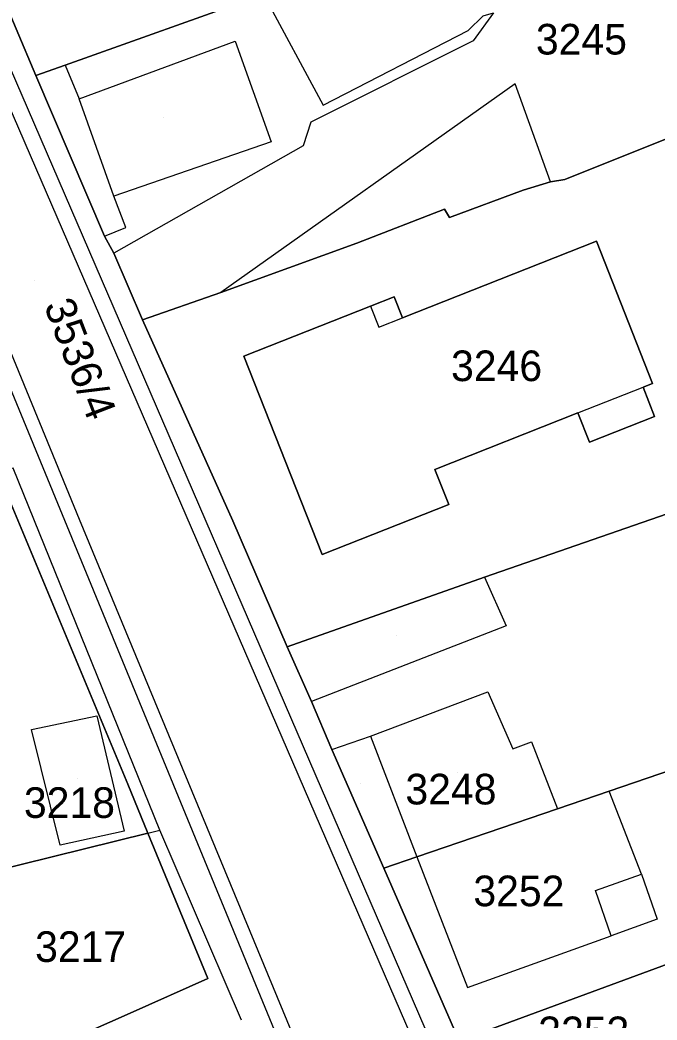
# Model space of a CAD drawing. Extents: x -262657 to -261595, y -1238015 to -1237156.
# Drawn here: x -261921.2 to -261879.5, y -1237814 to -1237748.7 of the extents above; entities that cross this region are included whole.
import ezdxf

# ---------------------------------------------------------------- set-up
doc = ezdxf.new("R2010")
doc.units = 0
for name, color, linetype in [('body_kn', 7, 'Continuous'), ('kladpar_druhypozemkov', 7, 'Continuous'), ('kladpar_hranice', 7, 'Continuous'), ('kladpar_parcelnecisla', 7, 'Continuous'), ('kladpar_plochy', 7, 'Continuous'), ('zappar_hrandruhpozemk', 7, 'Continuous')]:
    doc.layers.add(name, color=color, linetype=linetype)

msp = doc.modelspace()

# ---------------------------------------------------------------- linework, layer by layer
at = {"layer": 'body_kn'}
for p, q in [((-261891.88, -1237749.38), (-261891.88, -1237749.38)), ((-261907.09, -1237750.06), (-261907.09, -1237750.06)), ((-261907.09, -1237750.06), (-261907.09, -1237750.06)), ((-261891.54, -1237750.05), (-261891.54, -1237750.05)), ((-261918.2, -1237751.63), (-261918.2, -1237751.63)), ((-261918.2, -1237751.63), (-261918.2, -1237751.63)), ((-261920.12, -1237752.32), (-261920.12, -1237752.32)), ((-261920.12, -1237752.32), (-261920.12, -1237752.32)), ((-261888.8, -1237752.86), (-261888.8, -1237752.86)), ((-261917.29, -1237753.83), (-261917.29, -1237753.83)), ((-261917.29, -1237753.83), (-261917.29, -1237753.83)), ((-261901.34, -1237754.24), (-261901.34, -1237754.24)), ((-261902.16, -1237755.36), (-261902.16, -1237755.36)), ((-261904.74, -1237756.65), (-261904.74, -1237756.65)), ((-261902.66, -1237756.91), (-261902.66, -1237756.91)), ((-261886.5, -1237759.27), (-261886.5, -1237759.27)), ((-261886.5, -1237759.27), (-261886.5, -1237759.27)), ((-261885.56, -1237759.1), (-261885.56, -1237759.1)), ((-261888.28, -1237759.8), (-261888.28, -1237759.8)), ((-261915.03, -1237760.19), (-261915.03, -1237760.19)), ((-261915.03, -1237760.19), (-261915.03, -1237760.19)), ((-261893.41, -1237761.04), (-261893.41, -1237761.04)), ((-261893.1, -1237761.58), (-261893.1, -1237761.58)), ((-261914.24, -1237762.24), (-261914.24, -1237762.24)), ((-261915.64, -1237762.81), (-261915.64, -1237762.81)), ((-261915.64, -1237762.81), (-261915.64, -1237762.81)), ((-261883.49, -1237763.13), (-261883.49, -1237763.13)), ((-261899.15, -1237763.26), (-261899.15, -1237763.26)), ((-261915.03, -1237763.93), (-261915.03, -1237763.93)), ((-261908.04, -1237766.48), (-261908.04, -1237766.48)), ((-261896.7, -1237766.77), (-261896.7, -1237766.77)), ((-261898.25, -1237767.38), (-261898.25, -1237767.38)), ((-261898.25, -1237767.38), (-261898.25, -1237767.38)), ((-261913.16, -1237768.28), (-261913.16, -1237768.28)), ((-261896.16, -1237768.14), (-261896.16, -1237768.14)), ((-261897.7, -1237768.75), (-261897.7, -1237768.75)), ((-261906.54, -1237770.66), (-261906.54, -1237770.66)), ((-261880.44, -1237772.68), (-261880.44, -1237772.68)), ((-261879.82, -1237772.43), (-261879.82, -1237772.43)), ((-261884.7, -1237774.36), (-261884.7, -1237774.36)), ((-261884.7, -1237774.36), (-261884.7, -1237774.36)), ((-261879.69, -1237774.59), (-261879.69, -1237774.59)), ((-261883.94, -1237776.27), (-261883.94, -1237776.27)), ((-261894.04, -1237778.06), (-261894.04, -1237778.06)), ((-261894.04, -1237778.06), (-261894.04, -1237778.06)), ((-261893.14, -1237780.34), (-261893.14, -1237780.34)), ((-261917.3, -1237781.31), (-261917.3, -1237781.31)), ((-261907.24, -1237781.41), (-261907.24, -1237781.41)), ((-261901.42, -1237783.61), (-261901.42, -1237783.61)), ((-261890.8, -1237785.1), (-261890.8, -1237785.1)), ((-261890.8, -1237785.1), (-261890.8, -1237785.1)), ((-261889.39, -1237788.26), (-261889.39, -1237788.26)), ((-261903.69, -1237789.65), (-261903.69, -1237789.65)), ((-261903.69, -1237789.65), (-261903.69, -1237789.65)), ((-261890.58, -1237792.59), (-261890.58, -1237792.59)), ((-261902.12, -1237793.22), (-261902.12, -1237793.22)), ((-261916.13, -1237794.16), (-261916.13, -1237794.16)), ((-261920.41, -1237795.04), (-261920.41, -1237795.04)), ((-261898.26, -1237795.47), (-261898.26, -1237795.47)), ((-261887.73, -1237795.86), (-261887.73, -1237795.86)), ((-261900.78, -1237796.35), (-261900.78, -1237796.35)), ((-261900.78, -1237796.35), (-261900.78, -1237796.35)), ((-261888.95, -1237796.3), (-261888.95, -1237796.3)), ((-261914.12, -1237798.61), (-261914.12, -1237798.61)), ((-261882.66, -1237799.08), (-261882.66, -1237799.08)), ((-261886.03, -1237800.22), (-261886.03, -1237800.22)), ((-261914.35, -1237801.68), (-261914.35, -1237801.68)), ((-261912.03, -1237801.62), (-261912.03, -1237801.62)), ((-261912.8, -1237801.81), (-261912.8, -1237801.81)), ((-261912.8, -1237801.81), (-261912.8, -1237801.81)), ((-261918.54, -1237802.61), (-261918.54, -1237802.61)), ((-261918.54, -1237802.61), (-261918.54, -1237802.61)), ((-261895.22, -1237803.36), (-261895.22, -1237803.36)), ((-261895.22, -1237803.36), (-261895.22, -1237803.36)), ((-261897.39, -1237804.1), (-261897.39, -1237804.1)), ((-261897.39, -1237804.1), (-261897.39, -1237804.1)), ((-261880.55, -1237804.5), (-261880.55, -1237804.5)), ((-261880.55, -1237804.5), (-261880.55, -1237804.5)), ((-261883.54, -1237805.57), (-261883.54, -1237805.57)), ((-261882.53, -1237808.52), (-261882.53, -1237808.52)), ((-261908.88, -1237811.31), (-261908.88, -1237811.31)), ((-261891.91, -1237811.91), (-261891.91, -1237811.91)), ((-261913.97, -1237813.57), (-261913.97, -1237813.57))]:
    msp.add_line(p, q, dxfattribs=at)
at = {"layer": 'kladpar_druhypozemkov'}
for p, q in [((-261883.39, -1237749.05), (-261883.39, -1237749.05)), ((-261911.75, -1237755.06), (-261911.75, -1237755.06)), ((-261920.19, -1237765.72), (-261920.19, -1237765.72)), ((-261888.45, -1237770.3), (-261888.45, -1237770.3)), ((-261896.55, -1237788.9), (-261896.55, -1237788.9)), ((-261917.39, -1237798.27), (-261917.39, -1237798.27)), ((-261892.55, -1237797.88), (-261892.55, -1237797.88)), ((-261898.9, -1237798.57), (-261898.9, -1237798.57)), ((-261888.4, -1237804.98), (-261888.4, -1237804.98)), ((-261917.24, -1237808.41), (-261917.24, -1237808.41))]:
    msp.add_line(p, q, dxfattribs=at)
at = {"layer": 'kladpar_hranice'}
for points in [[(-261914.09, -1237816.76), (-261923.62, -1237819.21), (-261923.89, -1237818.34), (-261924, -1237817.96), (-261923.67, -1237817.87), (-261913.97, -1237813.57), (-261908.88, -1237811.31), (-261912.8, -1237801.81), (-261914.12, -1237798.61), (-261922.63, -1237778.24), (-261926.09, -1237769.65), (-261929.76, -1237759.16), (-261940.37, -1237728.85), (-261943.02, -1237721.29), (-261943.45, -1237719.94), (-261944.94, -1237715.14), (-261945.5, -1237713.33), (-261947.79, -1237697.89), (-261949.17, -1237690.86), (-261949.54, -1237688.95), (-261951.01, -1237681.71), (-261952.29, -1237673.66)], [(-261920.12, -1237752.32), (-261922.72, -1237746.19), (-261923.24, -1237745.09), (-261924.29, -1237741.53), (-261918.09, -1237739.63), (-261914.17, -1237738.53), (-261911.54, -1237737.64), (-261907.41, -1237736.41), (-261905.24, -1237747), (-261918.2, -1237751.63), (-261920.12, -1237752.32)], [(-261920.12, -1237752.32), (-261918.2, -1237751.63), (-261905.24, -1237747), (-261891.79, -1237742.14), (-261888.53, -1237740.9), (-261888.38, -1237741.32), (-261879.2, -1237737.96), (-261878.19, -1237737.65), (-261876.61, -1237737.16), (-261874.12, -1237742.17), (-261870.26, -1237752.98), (-261885.56, -1237759.1), (-261886.5, -1237759.27), (-261888.28, -1237759.8), (-261893.1, -1237761.58), (-261893.41, -1237761.04), (-261899.15, -1237763.26), (-261908.04, -1237766.48), (-261913.16, -1237768.28), (-261915.03, -1237763.93), (-261915.64, -1237762.81), (-261920.12, -1237752.32)], [(-261922.72, -1237746.19), (-261920.12, -1237752.32), (-261915.64, -1237762.81), (-261915.03, -1237763.93), (-261913.16, -1237768.28), (-261907.24, -1237781.41), (-261903.69, -1237789.65), (-261902.12, -1237793.22), (-261900.78, -1237796.35), (-261897.39, -1237804.1), (-261892.46, -1237815.38)], [(-261913.16, -1237768.28), (-261908.04, -1237766.48), (-261899.15, -1237763.26), (-261893.41, -1237761.04), (-261893.1, -1237761.58), (-261888.28, -1237759.8), (-261886.5, -1237759.27), (-261885.56, -1237759.1), (-261870.26, -1237752.98), (-261869.5, -1237752.69), (-261860.68, -1237774.55), (-261863.1, -1237775.49), (-261890.8, -1237785.1), (-261903.69, -1237789.65)], [(-261906.54, -1237770.66), (-261901.42, -1237783.61), (-261893.14, -1237780.34), (-261894.04, -1237778.06), (-261884.7, -1237774.36), (-261883.94, -1237776.27), (-261879.69, -1237774.59), (-261880.44, -1237772.68), (-261879.82, -1237772.43), (-261883.49, -1237763.13), (-261896.16, -1237768.14), (-261896.7, -1237766.77), (-261898.25, -1237767.38), (-261906.54, -1237770.66)], [(-261894.04, -1237778.06), (-261893.14, -1237780.34), (-261901.42, -1237783.61), (-261906.54, -1237770.66), (-261898.25, -1237767.38), (-261896.7, -1237766.77), (-261896.16, -1237768.14), (-261883.49, -1237763.13), (-261879.82, -1237772.43), (-261880.44, -1237772.68), (-261879.69, -1237774.59), (-261883.94, -1237776.27), (-261884.7, -1237774.36), (-261894.04, -1237778.06)], [(-261903.69, -1237789.65), (-261907.24, -1237781.41), (-261913.16, -1237768.28)], [(-261897.39, -1237804.1), (-261900.78, -1237796.35), (-261902.12, -1237793.22), (-261903.69, -1237789.65), (-261890.8, -1237785.1), (-261863.1, -1237775.49), (-261860.84, -1237781.14), (-261874.19, -1237785.8), (-261871.08, -1237795.12), (-261875.2, -1237796.53), (-261882.66, -1237799.08), (-261886.03, -1237800.22), (-261895.22, -1237803.36), (-261897.39, -1237804.1)], [(-261925.24, -1237804.88), (-261927.57, -1237779.48), (-261922.63, -1237778.24), (-261914.12, -1237798.61), (-261912.8, -1237801.81), (-261925.24, -1237804.88)], [(-261892.46, -1237815.38), (-261897.39, -1237804.1), (-261895.22, -1237803.36), (-261886.03, -1237800.22), (-261882.66, -1237799.08), (-261875.2, -1237796.53), (-261874.46, -1237799.37), (-261878.83, -1237801.48), (-261876.32, -1237809.44), (-261892.46, -1237815.38)], [(-261924.11, -1237817.62), (-261925.24, -1237804.88), (-261912.8, -1237801.81), (-261908.88, -1237811.31), (-261913.97, -1237813.57), (-261923.67, -1237817.87), (-261924, -1237817.96), (-261924.11, -1237817.62)], [(-261890.38, -1237820.3), (-261892.46, -1237815.38), (-261876.32, -1237809.44), (-261874, -1237808.64), (-261873.82, -1237809.05), (-261875.21, -1237809.56), (-261873.73, -1237813.58), (-261875.04, -1237813.91), (-261878.43, -1237816.1), (-261890.38, -1237820.3)]]:
    msp.add_lwpolyline(points, dxfattribs=at)
at = {"layer": 'kladpar_plochy'}
for p, q in [((-261885.56, -1237759.1), (-261870.26, -1237752.98)), ((-261888.28, -1237759.8), (-261886.5, -1237759.27)), ((-261886.5, -1237759.27), (-261885.56, -1237759.1)), ((-261893.1, -1237761.58), (-261888.28, -1237759.8)), ((-261899.15, -1237763.26), (-261893.41, -1237761.04)), ((-261893.41, -1237761.04), (-261893.1, -1237761.58)), ((-261883.49, -1237763.13), (-261896.16, -1237768.14)), ((-261879.82, -1237772.43), (-261883.49, -1237763.13)), ((-261908.04, -1237766.48), (-261899.15, -1237763.26)), ((-261913.16, -1237768.28), (-261908.04, -1237766.48)), ((-261896.7, -1237766.77), (-261898.25, -1237767.38)), ((-261896.16, -1237768.14), (-261896.7, -1237766.77)), ((-261898.25, -1237767.38), (-261906.54, -1237770.66)), ((-261907.24, -1237781.41), (-261913.16, -1237768.28)), ((-261906.54, -1237770.66), (-261901.42, -1237783.61)), ((-261880.44, -1237772.68), (-261879.82, -1237772.43)), ((-261879.69, -1237774.59), (-261880.44, -1237772.68)), ((-261894.04, -1237778.06), (-261884.7, -1237774.36)), ((-261884.7, -1237774.36), (-261883.94, -1237776.27)), ((-261883.94, -1237776.27), (-261879.69, -1237774.59)), ((-261863.1, -1237775.49), (-261890.8, -1237785.1)), ((-261893.14, -1237780.34), (-261894.04, -1237778.06)), ((-261901.42, -1237783.61), (-261893.14, -1237780.34)), ((-261903.69, -1237789.65), (-261907.24, -1237781.41)), ((-261890.8, -1237785.1), (-261903.69, -1237789.65))]:
    msp.add_line(p, q, dxfattribs=at)
for points in [[(-261923.67, -1237817.87), (-261913.97, -1237813.57), (-261908.88, -1237811.31), (-261912.8, -1237801.81), (-261914.12, -1237798.61), (-261922.63, -1237778.24), (-261926.09, -1237769.65), (-261929.76, -1237759.16), (-261940.37, -1237728.85)], [(-261922.72, -1237746.19), (-261920.12, -1237752.32), (-261915.64, -1237762.81), (-261915.03, -1237763.93), (-261913.16, -1237768.28), (-261907.24, -1237781.41), (-261903.69, -1237789.65), (-261902.12, -1237793.22), (-261900.78, -1237796.35), (-261897.39, -1237804.1), (-261892.46, -1237815.38)]]:
    msp.add_lwpolyline(points, dxfattribs=at)
for points in [[(-261920.12, -1237752.32), (-261922.72, -1237746.19), (-261923.24, -1237745.09), (-261924.29, -1237741.53), (-261918.09, -1237739.63), (-261914.17, -1237738.53), (-261911.54, -1237737.64), (-261907.41, -1237736.41), (-261905.24, -1237747), (-261918.2, -1237751.63)], [(-261920.12, -1237752.32), (-261918.2, -1237751.63), (-261905.24, -1237747), (-261891.79, -1237742.14), (-261888.53, -1237740.9), (-261888.38, -1237741.32), (-261879.2, -1237737.96), (-261878.19, -1237737.65), (-261876.61, -1237737.16), (-261874.12, -1237742.17), (-261870.26, -1237752.98), (-261885.56, -1237759.1), (-261886.5, -1237759.27), (-261888.28, -1237759.8), (-261893.1, -1237761.58), (-261893.41, -1237761.04), (-261899.15, -1237763.26), (-261908.04, -1237766.48), (-261913.16, -1237768.28), (-261915.03, -1237763.93), (-261915.64, -1237762.81)], [(-261894.04, -1237778.06), (-261893.14, -1237780.34), (-261901.42, -1237783.61), (-261906.54, -1237770.66), (-261898.25, -1237767.38), (-261896.7, -1237766.77), (-261896.16, -1237768.14), (-261883.49, -1237763.13), (-261879.82, -1237772.43), (-261880.44, -1237772.68), (-261879.69, -1237774.59), (-261883.94, -1237776.27), (-261884.7, -1237774.36)], [(-261897.39, -1237804.1), (-261900.78, -1237796.35), (-261902.12, -1237793.22), (-261903.69, -1237789.65), (-261890.8, -1237785.1), (-261863.1, -1237775.49), (-261860.84, -1237781.14), (-261874.19, -1237785.8), (-261871.08, -1237795.12), (-261875.2, -1237796.53), (-261882.66, -1237799.08), (-261886.03, -1237800.22), (-261895.22, -1237803.36)], [(-261925.24, -1237804.88), (-261927.57, -1237779.48), (-261922.63, -1237778.24), (-261914.12, -1237798.61), (-261912.8, -1237801.81)], [(-261892.46, -1237815.38), (-261897.39, -1237804.1), (-261895.22, -1237803.36), (-261886.03, -1237800.22), (-261882.66, -1237799.08), (-261875.2, -1237796.53), (-261874.46, -1237799.37), (-261878.83, -1237801.48), (-261876.32, -1237809.44)], [(-261924.11, -1237817.62), (-261925.24, -1237804.88), (-261912.8, -1237801.81), (-261908.88, -1237811.31), (-261913.97, -1237813.57), (-261923.67, -1237817.87), (-261924, -1237817.96)], [(-261890.38, -1237820.3), (-261892.46, -1237815.38), (-261876.32, -1237809.44), (-261874, -1237808.64), (-261873.82, -1237809.05), (-261875.21, -1237809.56), (-261873.73, -1237813.58), (-261875.04, -1237813.91), (-261878.43, -1237816.1)]]:
    msp.add_lwpolyline(points, close=True, dxfattribs=at)
at = {"layer": 'zappar_hrandruhpozemk'}
for p, q in [((-261924.51, -1237745.6), (-261870.74, -1237869.97)), ((-261917.29, -1237753.83), (-261907.09, -1237750.06)), ((-261907.09, -1237750.06), (-261904.74, -1237756.65)), ((-261918.2, -1237751.63), (-261917.29, -1237753.83)), ((-261888.8, -1237752.86), (-261908.04, -1237766.48)), ((-261886.5, -1237759.27), (-261888.8, -1237752.86)), ((-261915.03, -1237760.19), (-261917.29, -1237753.83)), ((-261904.74, -1237756.65), (-261915.03, -1237760.19)), ((-261902.66, -1237756.91), (-261915.03, -1237763.93)), ((-261926.63, -1237758.6), (-261917.3, -1237781.31)), ((-261898.25, -1237767.38), (-261897.7, -1237768.75)), ((-261897.7, -1237768.75), (-261896.16, -1237768.14)), ((-261884.7, -1237774.36), (-261880.44, -1237772.68)), ((-261890.8, -1237785.1), (-261889.39, -1237788.26)), ((-261889.39, -1237788.26), (-261902.12, -1237793.22)), ((-261918.54, -1237802.61), (-261920.41, -1237795.04)), ((-261900.78, -1237796.35), (-261898.26, -1237795.47)), ((-261898.26, -1237795.47), (-261895.22, -1237803.36)), ((-261906.69, -1237814.03), (-261912.03, -1237801.62)), ((-261895.22, -1237803.36), (-261891.91, -1237811.91))]:
    msp.add_line(p, q, dxfattribs=at)
for points in [[(-261857.29, -1237903.53), (-261871.7, -1237870.32), (-261925.44, -1237746.09), (-261934.35, -1237714.96)], [(-261875, -1237886.44), (-261927.55, -1237758.77), (-261932.46, -1237746.83)], [(-261905.24, -1237747), (-261901.34, -1237754.24), (-261891.88, -1237749.38)], [(-261891.88, -1237749.38), (-261890.88, -1237748.42), (-261890.21, -1237748.21), (-261891.54, -1237750.05), (-261902.16, -1237755.36), (-261902.66, -1237756.91)], [(-261915.64, -1237762.81), (-261914.24, -1237762.24), (-261915.03, -1237760.19)], [(-261912.8, -1237801.81), (-261912.03, -1237801.62), (-261921.61, -1237777.97), (-261922.63, -1237778.24)], [(-261917.3, -1237781.31), (-261875.05, -1237883.26), (-261864.96, -1237906.9)], [(-261898.26, -1237795.47), (-261890.58, -1237792.59), (-261888.95, -1237796.3)], [(-261920.41, -1237795.04), (-261916.13, -1237794.16), (-261914.35, -1237801.68), (-261918.54, -1237802.61)], [(-261888.95, -1237796.3), (-261887.73, -1237795.86), (-261886.03, -1237800.22)], [(-261883.54, -1237805.57), (-261880.55, -1237804.5), (-261882.66, -1237799.08)], [(-261880.55, -1237804.5), (-261879.53, -1237807.43), (-261882.53, -1237808.52)], [(-261891.91, -1237811.91), (-261882.53, -1237808.52), (-261883.54, -1237805.57)]]:
    msp.add_lwpolyline(points, dxfattribs=at)

# ---------------------------------------------------------------- texts
at = {"layer": 'kladpar_parcelnecisla'}
for s, p in [('3245', (-261887.444, -1237750.94)), ('3246', (-261892.989, -1237772.28)), ('3248', (-261895.973, -1237799.94)), ('3218', (-261920.903, -1237800.82)), ('3252', (-261891.531, -1237806.59)), ('3217', (-261920.172, -1237810.23)), ('3253', (-261887.287, -1237815.8))]:
    msp.add_text(s, height=2, dxfattribs=at).set_placement(p)
msp.add_text('3536/4', height=2, rotation=291, dxfattribs=at).set_placement((-261919.615, -1237767.338))

doc.saveas('drawing.dxf')
